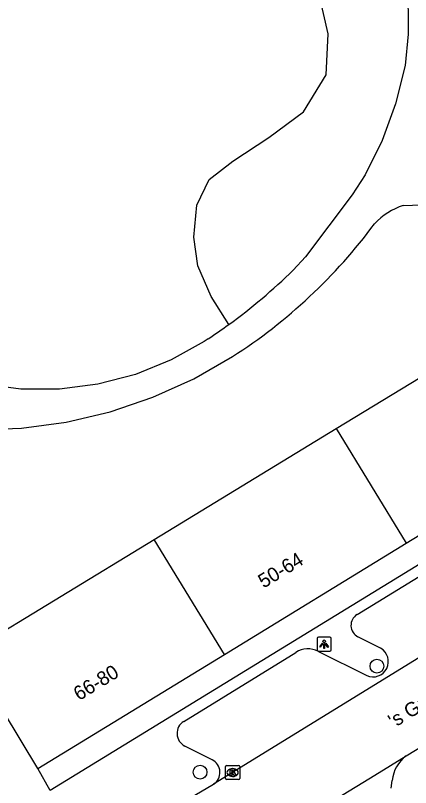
# Model space of a CAD drawing. Extents: x 159888 to 160757, y 384031 to 384746.
# Drawn here: x 160236.6 to 160264.5, y 384559.5 to 384614.1 of the extents above; entities that cross this region are included whole.
import ezdxf

# ---------------------------------------------------------------- set-up
doc = ezdxf.new("R2010")
doc.units = 0
for name, color, linetype in [('IMGEO_Boom', 7, 'Continuous'), ('IMGEO_Groenvoorziening', 7, 'Continuous'), ('IMGEO_Kolk', 7, 'Continuous'), ('IMGEO_Lichtpunt', 7, 'Continuous'), ('IMGEO_Openbare_ruimte_label', 7, 'Continuous'), ('IMGEO_Pand', 7, 'Continuous'), ('IMGEO_Pand_nummerreeks', 7, 'Continuous'), ('IMGEO_Rijbaan_lokaal_open', 7, 'Continuous'), ('IMGEO_Voetpad_gesloten', 7, 'Continuous'), ('IMGEO_Voetpad_open', 7, 'Continuous')]:
    doc.layers.add(name, color=color, linetype=linetype)

msp = doc.modelspace()

# ---------------------------------------------------------------- linework, layer by layer
at = {"layer": 'IMGEO_Boom'}
for centre in [(160262.167, 384568.089), (160249.646, 384560.585)]:
    msp.add_circle(centre, 0.489, dxfattribs=at)
at = {"layer": 'IMGEO_Groenvoorziening'}
msp.add_lwpolyline([(160251.685, 384592.251), (160250.44, 384594.226), (160249.496, 384596.403), (160249.206, 384598.436), (160249.424, 384600.686), (160250.295, 384602.501), (160251.964, 384603.807), (160254.505, 384605.477), (160256.973, 384607.292), (160258.57, 384609.905), (160258.715, 384612.809), (160257.989, 384616.003), (160256.465, 384619.342), (160253.416, 384622.899), (160253.706, 384624.858), (160255.957, 384626.891), (160257.848, 384627.567)], dxfattribs=at)
at = {"layer": 'IMGEO_Kolk'}
for p, q in [((160251.449, 384560.138), (160251.449, 384560.99)), ((160251.524, 384561.064), (160252.376, 384561.064)), ((160251.937, 384560.844), (160251.962, 384560.844)), ((160252.45, 384560.99), (160252.45, 384560.138)), ((160252.376, 384560.064), (160251.524, 384560.064)), ((160251.96, 384560.284), (160251.935, 384560.284))]:
    msp.add_line(p, q, dxfattribs=at)
for points in [[(160251.449, 384560.138), (160251.449, 384560.99)], [(160251.524, 384561.064), (160252.376, 384561.064)], [(160251.77, 384560.764), (160251.893, 384560.764), (160251.893, 384560.613), (160252.023, 384560.764), (160252.187, 384560.764), (160252.041, 384560.613), (160252.194, 384560.364), (160252.042, 384560.364), (160251.957, 384560.528), (160251.893, 384560.461), (160251.893, 384560.364), (160251.77, 384560.364), (160251.77, 384560.764)], [(160252.45, 384560.99), (160252.45, 384560.138)], [(160252.376, 384560.064), (160251.524, 384560.064)]]:
    msp.add_lwpolyline(points, dxfattribs=at)
for centre, start, end in [((160251.526, 384560.988), 91.552, 178.448), ((160251.526, 384560.988), 91.552, 178.448), ((160252.374, 384560.988), 1.552, 88.448), ((160252.374, 384560.988), 1.552, 88.448), ((160251.526, 384560.14), 181.552, 268.448), ((160251.526, 384560.14), 181.552, 268.448), ((160252.374, 384560.14), 271.552, 358.448), ((160252.374, 384560.14), 271.552, 358.448)]:
    msp.add_arc(centre, 0.0765, start, end, dxfattribs=at)
for centre, major_axis, ratio, start_param, end_param in [((160251.936, 384560.564), (-0.387, 0.002), 0.722429, 4.712389, 7.853982), ((160251.961, 384560.564), (-0.39, 0.002), 0.717154, 1.570796, 4.712389)]:
    msp.add_ellipse(centre, major_axis=major_axis, ratio=ratio, start_param=start_param, end_param=end_param, dxfattribs=at)
at = {"layer": 'IMGEO_Lichtpunt'}
for p, q in [((160257.927, 384570.044), (160257.927, 384569.237)), ((160257.927, 384570.044), (160257.927, 384569.237)), ((160258.829, 384570.139), (160258.021, 384570.139)), ((160258.829, 384570.139), (160258.021, 384570.139)), ((160258.923, 384569.237), (160258.923, 384570.044)), ((160258.923, 384569.237), (160258.923, 384570.044)), ((160258.021, 384569.143), (160258.829, 384569.143)), ((160258.021, 384569.143), (160258.829, 384569.143))]:
    msp.add_line(p, q, dxfattribs=at)
for points in [[(160258.301, 384569.708), (160258.34, 384569.68), (160258.152, 384569.418), (160258.114, 384569.445), (160258.301, 384569.708)], [(160258.403, 384569.66), (160258.45, 384569.66), (160258.45, 384569.338), (160258.403, 384569.338), (160258.403, 384569.66)], [(160258.513, 384569.68), (160258.551, 384569.707), (160258.738, 384569.445), (160258.699, 384569.417), (160258.513, 384569.68)]]:
    msp.add_lwpolyline(points, dxfattribs=at)
msp.add_circle((160258.426, 384569.842), 0.0994, dxfattribs=at)
for centre, start, end in [((160258.021, 384570.044), 90, 180), ((160258.021, 384570.044), 90, 180), ((160258.829, 384570.044), 0, 90), ((160258.829, 384570.044), 0, 90), ((160258.021, 384569.237), 180, 270), ((160258.021, 384569.237), 180, 270), ((160258.829, 384569.237), 270, 0), ((160258.829, 384569.237), 270, 360)]:
    msp.add_arc(centre, 0.0946, start, end, dxfattribs=at)
at = {"layer": 'IMGEO_Pand'}
for points in [[(160259.284, 384584.888), (160272.37, 384592.846)], [(160246.396, 384577.051), (160259.284, 384584.888)], [(160259.284, 384584.888), (160264.236, 384576.779)], [(160264.236, 384576.779), (160277.307, 384584.762)], [(160233.193, 384569.021), (160246.396, 384577.051)], [(160251.363, 384568.918), (160246.396, 384577.051)], [(160251.363, 384568.918), (160264.236, 384576.779)], [(160238.163, 384560.857), (160233.193, 384569.021)], [(160238.163, 384560.857), (160251.363, 384568.918)]]:
    msp.add_lwpolyline(points, dxfattribs=at)
at = {"layer": 'IMGEO_Rijbaan_lokaal_open'}
for points in [[(160314.113, 384598.543), (160302.345, 384591.293), (160284.124, 384580.182), (160267.279, 384569.999), (160250.599, 384559.732)], [(160264.233, 384561.732), (160267.235, 384563.57)], [(160245.48, 384550.279), (160262.023, 384560.378), (160264.233, 384561.732)], [(160242.452, 384554.96), (160250.599, 384559.732)]]:
    msp.add_lwpolyline(points, dxfattribs=at)
at = {"layer": 'IMGEO_Voetpad_gesloten'}
for points in [[(160257.848, 384627.567), (160259.733, 384626.078), (160261.379, 384624.014), (160262.194, 384622.559), (160263.498, 384619.607), (160264.045, 384617.89), (160264.38, 384614.464), (160264.387, 384612.775), (160264.177, 384610.576), (160263.49, 384607.865), (160262.532, 384605.262), (160261.323, 384602.838), (160260.411, 384601.411), (160257.121, 384597.034), (160256.232, 384596.094)], [(160264.028, 384600.667), (160266.034, 384600.741), (160268.826, 384600.771)], [(160250.216, 384591.237), (160249.938, 384591.056), (160247.599, 384589.743), (160245.072, 384588.72), (160242.412, 384588.024), (160239.685, 384587.676), (160236.959, 384587.68), (160234.299, 384588.023)], [(160233.849, 384584.805), (160237.001, 384584.919), (160240.157, 384585.341), (160243.272, 384586.07), (160246.301, 384587.099), (160249.202, 384588.411), (160251.938, 384589.981)]]:
    msp.add_lwpolyline(points, dxfattribs=at)
for centre, radius, start, end in [((160265.599, 384595.96), 4.962, 108.4592, 136.5307), ((160231.446, 384622.012), 38.025, 302.6094, 323.463), ((160228.263, 384624.576), 39.918, 305.927, 314.4801), ((160227.649, 384625.502), 41.029, 303.3695, 305.8624)]:
    msp.add_arc(centre, radius, start, end, dxfattribs=at)
at = {"layer": 'IMGEO_Voetpad_open'}
for points in [[(160312.059, 384603.995), (160239.027, 384559.29)], [(160260.757, 384571.733), (160264.729, 384574.179), (160269.651, 384577.155)], [(160262.429, 384569.359), (160260.825, 384570.162)], [(160248.488, 384564.182), (160256.416, 384569.062)], [(160258.02, 384569.132), (160261.449, 384567.415)], [(160250.503, 384561.465), (160248.564, 384562.436)], [(160239.027, 384559.29), (160238.163, 384560.857)], [(160263.182, 384559.455), (160263.246, 384560.005)]]:
    msp.add_lwpolyline(points, dxfattribs=at)
for centre, radius, start, end in [((160261.228, 384570.966), 0.9, 121.5561, 243.4009), ((160261.884, 384568.415), 1.09, 246.5142, 59.979), ((160257.281, 384567.655), 1.652, 63.4205, 121.5772), ((160249.012, 384563.33), 1, 121.6143, 243.3705), ((160265.704, 384559.746), 2.472, 126.5236, 173.9795), ((160250.052, 384560.571), 1.001, 303.1001, 63.2413)]:
    msp.add_arc(centre, radius, start, end, dxfattribs=at)

# ---------------------------------------------------------------- texts
at = {"layer": 'IMGEO_Openbare_ruimte_label'}
msp.add_text("'s Gravesandestraat", height=1, rotation=31.4649, dxfattribs=at).set_placement((160263.359, 384563.676))
at = {"layer": 'IMGEO_Pand_nummerreeks'}
for s, rotation, p in [('50-64', 31.3689, (160254.143, 384573.567)), ('66-80', 31.4752, (160241.075, 384565.609))]:
    msp.add_text(s, height=1, rotation=rotation, dxfattribs=at).set_placement(p)

doc.saveas('drawing.dxf')
